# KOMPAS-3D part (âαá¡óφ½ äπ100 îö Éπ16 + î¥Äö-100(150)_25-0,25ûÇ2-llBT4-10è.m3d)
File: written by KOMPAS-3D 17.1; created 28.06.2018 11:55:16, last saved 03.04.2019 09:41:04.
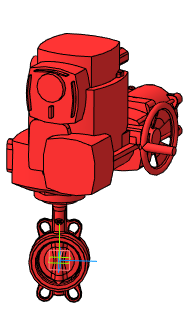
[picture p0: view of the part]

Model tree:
1. Операция без истории:2  (labels: Гранвэл Ду100 МФ Ру16 + SQ05.2 380В; SYSTEM_PROPERTY_ADDITIONAL_FOR:20.000000)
